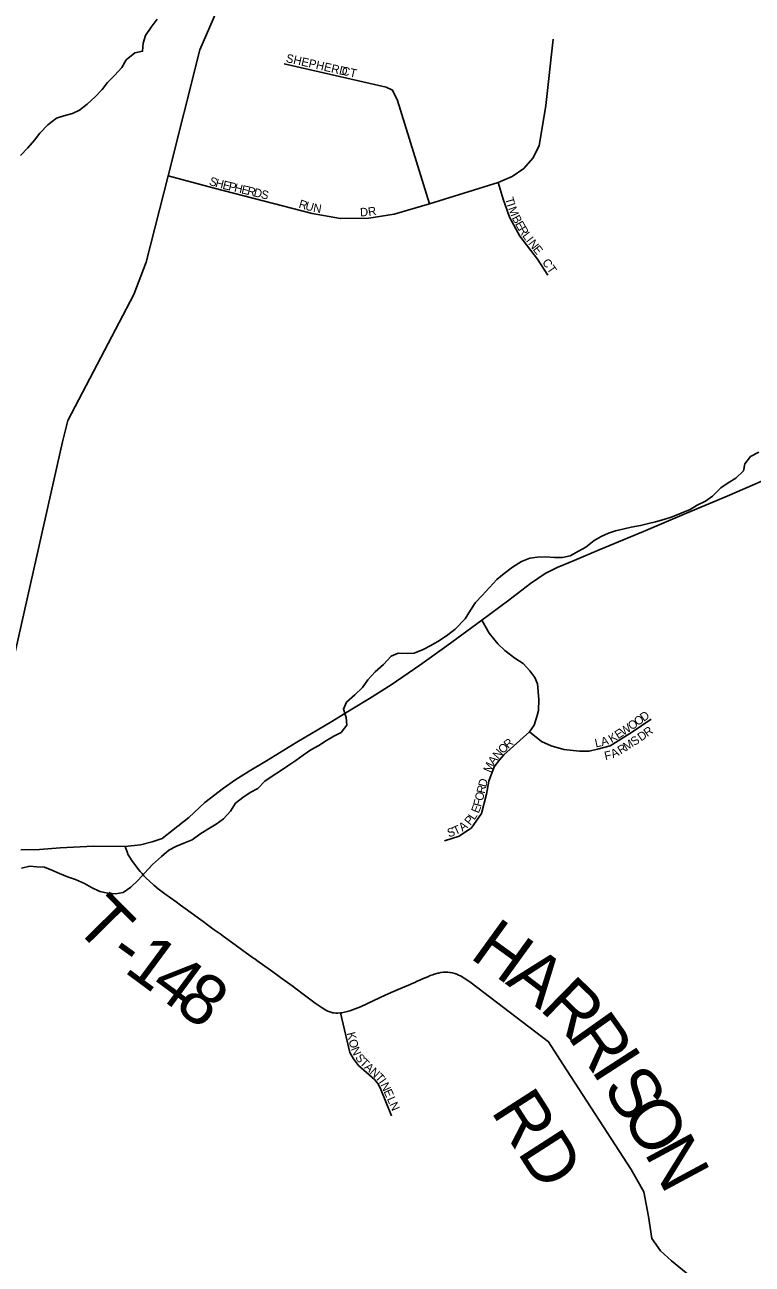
# Model space of a CAD drawing. Extents: x 0 to 1064, y 0 to 440.
# Drawn here: x 222.59 to 235.65, y 62.77 to 85.02 of the extents above; entities that cross this region are included whole.
import ezdxf

# ---------------------------------------------------------------- set-up
doc = ezdxf.new("R2010")
doc.units = 0
for name, color, linetype in [('GM_X_Minor_River', 7, 'Continuous'), ('GM_X_State_Route', 7, 'Continuous'), ('GM_X_Township_Road', 7, 'Continuous'), ('GM_X_Township_Road_Text', 7, 'Continuous'), ('GM_X_Township_Subdivision', 7, 'Continuous'), ('GM_X_Township_Subdivision_Text', 7, 'Continuous')]:
    doc.layers.add(name, color=color, linetype=linetype)

msp = doc.modelspace()

# ---------------------------------------------------------------- linework, layer by layer
at = {"layer": 'GM_X_Minor_River'}
for points in [[(224.964, 85.121), (224.858, 84.977), (224.758, 84.827), (224.713, 84.687), (224.705, 84.542), (224.564, 84.514), (224.41, 84.388), (224.329, 84.25), (224.205, 84.112), (224.075, 83.981), (223.976, 83.855), (223.852, 83.723), (223.71, 83.591), (223.574, 83.484), (223.446, 83.426), (223.293, 83.385), (223.159, 83.339), (223.005, 83.22), (222.862, 83.07), (222.763, 82.944)], [(222.763, 82.944), (222.645, 82.806), (222.515, 82.669)], [(235.77, 77.348), (235.623, 77.271), (235.523, 77.139), (235.497, 77.012), (235.361, 76.88), (235.22, 76.797), (235.09, 76.708), (234.942, 76.559), (234.813, 76.464), (234.666, 76.393), (234.537, 76.316), (234.378, 76.252), (234.218, 76.187), (234.066, 76.135), (233.919, 76.095), (233.791, 76.067), (233.644, 76.032), (233.48, 75.999), (233.352, 75.97), (233.199, 75.936), (233.071, 75.89), (232.942, 75.831), (232.813, 75.76), (232.665, 75.641), (232.536, 75.57), (232.383, 75.487), (232.243, 75.453), (232.103, 75.455), (231.939, 75.47), (231.799, 75.46), (231.659, 75.444), (231.512, 75.386), (231.346, 75.279), (231.198, 75.166), (231.069, 75.059), (230.933, 74.915), (230.803, 74.771), (230.685, 74.646), (230.591, 74.507), (230.498, 74.357), (230.318, 74.171), (230.189, 74.064), (230.035, 73.963), (229.882, 73.874), (229.741, 73.804), (229.582, 73.74), (229.454, 73.729), (229.296, 73.738), (229.167, 73.685), (229.031, 73.536), (228.883, 73.404), (228.747, 73.261), (228.653, 73.122), (228.517, 72.991), (228.369, 72.86), (228.312, 72.733), (228.358, 72.586), (228.374, 72.446), (228.269, 72.314), (228.14, 72.249), (228.005, 72.173), (227.87, 72.078), (227.729, 72.001), (227.587, 71.906), (227.458, 71.811), (227.316, 71.716)], [(227.316, 71.716), (227.181, 71.627), (227.034, 71.532), (226.898, 71.443), (226.775, 71.311), (226.634, 71.234), (226.504, 71.145), (226.375, 71.044), (226.281, 70.9), (226.158, 70.762), (226.028, 70.667), (225.875, 70.578), (225.734, 70.489), (225.598, 70.388), (225.445, 70.33), (225.304, 70.265), (225.175, 70.2), (225.046, 70.087), (224.885, 69.944), (224.737, 69.788), (224.625, 69.662), (224.496, 69.537), (224.354, 69.442), (224.226, 69.42), (224.08, 69.428), (223.935, 69.461), (223.79, 69.53), (223.664, 69.605), (223.501, 69.674), (223.356, 69.725), (223.211, 69.782), (223.072, 69.845), (222.945, 69.896), (222.806, 69.904), (222.678, 69.912), (222.532, 69.878)]]:
    msp.add_lwpolyline(points, dxfattribs=at)
at = {"layer": 'GM_X_State_Route'}
msp.add_lwpolyline([(222.518, 70.206), (222.851, 70.216), (223.224, 70.241), (223.826, 70.271), (224.39, 70.268), (224.666, 70.296), (224.874, 70.349), (225.058, 70.414), (225.254, 70.565), (225.536, 70.786), (225.822, 71.06), (226.156, 71.317), (226.377, 71.472), (226.618, 71.619), (226.928, 71.807), (227.472, 72.138), (228.105, 72.514), (228.46, 72.73), (228.779, 72.926), (229.171, 73.167), (229.681, 73.523), (230.171, 73.87), (230.799, 74.332), (231.282, 74.687), (231.674, 74.99), (231.936, 75.168), (232.148, 75.278), (232.457, 75.4), (232.902, 75.591), (233.702, 75.921), (234.473, 76.251), (235.201, 76.556), (235.836, 76.832)], dxfattribs=at)
at = {"layer": 'GM_X_Township_Road'}
for points in [[(222.171, 72.586), (222.266, 73.091), (223.264, 77.53), (223.365, 77.916), (224.549, 80.175), (224.771, 80.759), (225.162, 82.306), (225.734, 84.566), (226.09, 85.395), (226.206, 85.636), (226.333, 85.852), (226.734, 86.279), (226.976, 86.751), (227.402, 87.688), (227.775, 88.482), (228.291, 89.653), (228.585, 90.64), (228.902, 92.053), (229.253, 93.162), (229.655, 94.135), (231.335, 97.797)], [(224.39, 70.268), (224.434, 70.151), (224.442, 70.13), (224.457, 70.102), (224.514, 70.014), (224.632, 69.857), (224.664, 69.818), (224.696, 69.78), (224.729, 69.743), (224.763, 69.707), (224.908, 69.571), (224.985, 69.508), (225.104, 69.418), (225.307, 69.274), (225.388, 69.215), (225.469, 69.157), (225.75, 68.95), (225.79, 68.921), (225.871, 68.862), (225.992, 68.774), (226.113, 68.686), (226.153, 68.657), (226.194, 68.628), (226.234, 68.599), (226.638, 68.306), (226.678, 68.277), (226.698, 68.263), (226.719, 68.248), (226.759, 68.219), (227.003, 68.046), (227.044, 68.017), (227.245, 67.87), (227.406, 67.752), (227.446, 67.723), (227.486, 67.693), (227.566, 67.633), (227.685, 67.542), (227.806, 67.453), (227.93, 67.37), (227.996, 67.329), (228.032, 67.311), (228.069, 67.297), (228.104, 67.287), (228.121, 67.284), (228.139, 67.281), (228.175, 67.278), (228.212, 67.278), (228.26, 67.283), (228.28, 67.283), (228.33, 67.292), (228.38, 67.304), (228.428, 67.318), (228.571, 67.371), (228.618, 67.39), (228.73, 67.441), (228.961, 67.548), (229.064, 67.596), (229.213, 67.664), (229.452, 67.766), (229.499, 67.787), (229.545, 67.808), (229.592, 67.829), (229.638, 67.85), (229.684, 67.87), (229.731, 67.891), (229.825, 67.93), (229.872, 67.949), (229.92, 67.966), (229.944, 67.974), (229.968, 67.981), (230.004, 67.991), (230.017, 67.995), (230.061, 68.007), (230.103, 68.012), (230.144, 68.014), (230.184, 68.013), (230.225, 68.008), (230.267, 68), (230.312, 67.987), (230.347, 67.975), (230.381, 67.96), (230.414, 67.943), (230.446, 67.925), (230.481, 67.905), (230.563, 67.85), (230.604, 67.822), (231.997, 66.763), (232.25, 66.36), (233.479, 64.469), (233.708, 64.066), (233.788, 63.623), (233.853, 63.23), (234.007, 63.011), (234.203, 62.83)], [(234.203, 62.83), (234.206, 62.827), (235.558, 61.724)]]:
    msp.add_lwpolyline(points, dxfattribs=at)
at = {"layer": 'GM_X_Township_Subdivision'}
for points in [[(225.162, 82.306), (225.988, 82.086), (227.75, 81.629), (228.256, 81.538), (228.765, 81.549), (229.222, 81.621), (229.858, 81.805), (231.09, 82.184), (231.34, 82.293), (231.551, 82.44), (231.714, 82.625), (231.825, 82.846), (231.944, 83.568), (232.077, 84.762)], [(227.247, 84.317), (229.081, 83.898), (229.194, 83.842), (229.282, 83.657), (229.858, 81.805)], [(231.981, 80.525), (231.795, 80.809), (231.479, 81.226), (231.293, 81.562), (231.182, 81.888), (231.09, 82.184)], [(230.127, 70.37), (230.391, 70.455), (230.611, 70.604), (230.789, 70.86), (230.881, 71.209), (230.924, 71.443), (231.016, 71.699), (231.123, 71.827), (231.194, 71.913), (231.656, 72.324), (231.735, 72.448), (231.792, 72.617), (231.814, 72.71), (231.82, 72.908), (231.794, 73.19), (231.747, 73.3), (231.66, 73.421), (231.539, 73.552), (231.391, 73.649), (231.21, 73.783), (231.083, 73.904), (230.929, 74.095), (230.799, 74.332)], [(233.84, 72.553), (233.505, 72.325), (233.1, 72.076), (232.874, 72.015), (232.724, 71.979), (232.552, 71.979), (232.267, 72.009), (232.044, 72.075), (231.867, 72.155), (231.656, 72.324)], [(229.174, 65.433), (228.971, 65.937), (228.93, 66.011), (228.868, 66.083), (228.582, 66.338), (228.494, 66.453), (228.429, 66.57), (228.282, 67.178), (228.266, 67.257), (228.26, 67.283)]]:
    msp.add_lwpolyline(points, dxfattribs=at)

# ---------------------------------------------------------------- texts
at = {"layer": 'GM_X_Township_Road_Text'}
for s, height, rotation, p in [('T', 0.909, 314.5909, (223.447, 68.839)), ('H', 0.909, 324.1181, (230.56, 68.28)), ('-', 0.909, 324.1906, (224.051, 68.247)), ('1', 0.909, 323.5017, (224.351, 68.03)), ('A', 0.909, 322.6682, (231.204, 67.814)), ('4', 0.909, 323.5424, (224.802, 67.696)), ('8', 0.909, 323.6918, (225.254, 67.362)), ('R', 0.909, 315.552, (231.817, 67.349)), ('R', 0.909, 305.3086, (232.322, 66.859)), ('I', 0.909, 302.8609, (232.748, 66.258)), ('S', 0.909, 302.8334, (232.951, 65.944)), ('RD', 0.9091, 302.7352, (230.948, 65.518)), ('O', 0.909, 302.6383, (233.283, 65.43)), ('N', 0.909, 298.2139, (233.705, 64.772))]:
    msp.add_text(s, height=height, rotation=rotation, dxfattribs=at).set_placement(p)
at = {"layer": 'GM_X_Township_Subdivision_Text'}
for s, height, rotation, p in [('SHEPHERD', 0.1515, 347.1229, (227.269, 84.351)), ('CT', 0.1515, 347.4789, (228.269, 84.124)), ('S', 0.152, 340.8479, (225.887, 82.15)), ('H', 0.152, 345.3256, (226, 82.111)), ('E', 0.152, 346.3502, (226.132, 82.076)), ('P', 0.152, 346.3481, (226.236, 82.051)), ('H', 0.152, 346.3402, (226.34, 82.026)), ('E', 0.152, 346.366, (226.469, 81.995)), ('R', 0.152, 346.3465, (226.573, 81.969)), ('D', 0.152, 346.3549, (226.689, 81.941)), ('S', 0.152, 346.366, (226.819, 81.91)), ('R', 0.152, 343.4543, (227.498, 81.737)), ('T', 0.152, 285.9717, (231.213, 81.899)), ('U', 0.152, 344.2166, (227.615, 81.703)), ('N', 0.152, 350.1056, (227.76, 81.663)), ('D', 0.152, 1.2895, (228.61, 81.579)), ('R', 0.152, 9.0803, (228.766, 81.584)), ('I', 0.152, 288.3418, (231.244, 81.79)), ('M', 0.152, 290.2499, (231.267, 81.722)), ('B', 0.152, 298.2136, (231.332, 81.551)), ('E', 0.152, 299.4551, (231.39, 81.442)), ('R', 0.152, 301.1608, (231.445, 81.345)), ('L', 0.152, 307.0217, (231.516, 81.228)), ('I', 0.152, 308.1062, (231.583, 81.141)), ('N', 0.152, 308.1414, (231.624, 81.088)), ('E', 0.152, 308.1541, (231.706, 80.983)), ('CT', 0.1515, 305.5436, (231.873, 80.753)), ('O', 0.152, 35.1648, (233.487, 72.349)), ('O', 0.152, 35.7434, (233.597, 72.426)), ('D', 0.152, 35.775, (233.705, 72.504)), ('K', 0.152, 31.3975, (233.128, 72.122)), ('E', 0.152, 32.3874, (233.244, 72.193)), ('W', 0.152, 32.7263, (233.335, 72.251)), ('D', 0.152, 34.746, (233.658, 72.151)), ('R', 0.152, 35.4055, (233.769, 72.229)), ('O', 0.152, 43.3149, (231.175, 71.924)), ('R', 0.152, 41.6497, (231.271, 72.015)), ('L', 0.152, 12.2799, (232.844, 72.045)), ('A', 0.152, 15.0018, (232.956, 72.069)), ('R', 0.152, 31.8781, (233.292, 71.916)), ('M', 0.152, 32.4635, (233.395, 71.981)), ('S', 0.152, 33.569, (233.533, 72.068)), ('A', 0.152, 53.0776, (231.013, 71.721)), ('N', 0.152, 49.4556, (231.091, 71.826)), ('F', 0.152, 12.6711, (233.016, 71.816)), ('A', 0.152, 24.863, (233.153, 71.851)), ('M', 0.152, 66.8014, (230.955, 71.583)), ('D', 0.152, 75.6191, (230.874, 71.324)), ('O', 0.152, 75.2682, (230.812, 71.075)), ('R', 0.152, 77.0007, (230.847, 71.208)), ('E', 0.152, 68.6976, (230.74, 70.854)), ('F', 0.152, 74.9331, (230.784, 70.971)), ('P', 0.152, 51.2651, (230.588, 70.639)), ('L', 0.152, 55.9865, (230.663, 70.733)), ('S', 0.152, 17.9424, (230.203, 70.431)), ('T', 0.152, 23.4181, (230.319, 70.47)), ('A', 0.152, 36.2095, (230.449, 70.53)), ('K', 0.152, 283.9726, (228.371, 66.916)), ('O', 0.152, 283.9726, (228.403, 66.787)), ('N', 0.152, 292.904, (228.443, 66.633)), ('S', 0.152, 307.0038, (228.515, 66.475)), ('T', 0.152, 315.0831, (228.595, 66.372)), ('A', 0.152, 317.5022, (228.676, 66.292)), ('N', 0.152, 317.7415, (228.774, 66.202)), ('T', 0.152, 312.2553, (228.87, 66.115)), ('I', 0.152, 305.497, (228.939, 66.039)), ('N', 0.152, 294.8148, (228.974, 65.992)), ('E', 0.152, 294.0346, (229.03, 65.871)), ('L', 0.152, 293.9736, (229.089, 65.737)), ('N', 0.152, 293.9447, (229.133, 65.64))]:
    msp.add_text(s, height=height, rotation=rotation, dxfattribs=at).set_placement(p)

doc.saveas('drawing.dxf')
